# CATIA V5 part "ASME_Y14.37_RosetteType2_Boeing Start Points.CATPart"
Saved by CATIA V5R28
Part number: 333X3333-303
Revision: --
Nomenclature: ASME_Y14.37_RosetteType2
Bounding box of the stored display mesh (mm): x -188.298 to 149.059, y -714.612 to 664.697, z 0 to 91.639
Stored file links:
  C:\Users\jvl2147\Documents\AP242 testing\Composite Example Parts for PER\Start Points - CWB\ASME_Y14.37_RosetteType2_Boeing Start Points.CATPart
  \\NW\Data\MSE-Composites\ASME Y14.37\ASME Y-14.37_COMPOSITES.CATMaterial
  C:\Users\jvl2147\AppData\Local\DassaultSystemes\CATTemp\B28SP3PRALL\333X3333-303_Ply Group - 333X3333-303_StaggerOrigin.txt
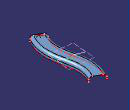
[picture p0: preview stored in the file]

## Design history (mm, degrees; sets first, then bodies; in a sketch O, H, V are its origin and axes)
AxisSystem1 "ROSETTE COORDINATE SYSTEM": origin (-72.9205, -637.9645, 93.98), X (0.5026, 0.8645, 0), Y (-0.8645, 0.5026, 0), Z (0, 0, 1)
CompParametersFeature1 "CATCoParametersFeatName": Value 0, Value 45, Value -45, Value 90
CompEOPGroupFeature1 "CATCoEOPGroupFeatName"
CompStacking1 "Stacking"
CompIsoThickAreasGroup1 "CATCoIsoThickAreasGroupFeatName": RefAddThickness 0
TTRSSet1
f4a2d38f3ddc11d3a929006094b99c4b_11 "CATTPSSet"
CompReviewTools1 "Review tools"
Set1 "CONSTRUCTION GEOMETRY"
  Set2 "CONSTRUCTION - LAMINATE REFERENCE SURFACE"
    Sketch1 on xy-plane, origin (0, 0, 0), H (1, 0, 0), V (0, 1, 0)
      spline S1 through (-79.505, -649.09) (21.2912, -260.3998) (-51.6257, 228.8061) (37.963, 602.845)
    Plane1: type Normal, Curve Sketch1, RefPoint vertex of Sketch1, Ratio 0
    Sketch2 on Plane1, origin (-464.3095, -417.3341, 0), H (-0.8566, 0.5159, 0), V (0, 0, 1)
      line L1 (-525.4052, 91.6386) -> (-373.0052, 91.6386)
      line L2 (-322.2052, 40.8386) -> (-322.2052, 0)
      line L3 (-576.2052, 0) -> (-576.2052, 40.8386)
      reference projected point E1 (-449.2052, 0) from vertex of Sketch1
      reference projected point E2 (-449.2052, 0) from vertex of Sketch1
      arc A1 centre (-373.0052, 40.8386) radius 50.8 from (-373.0052, 91.6386) to (-322.2052, 40.8386) cw
      arc A2 centre (-525.4052, 40.8386) radius 50.8 from (-576.2052, 40.8386) to (-525.4052, 91.6386) cw
      distance E1 L2 = 127
      distance E2 L3 = 127
      radius A1 = 50.8
      radius A2 = 50.8
      horizontal: L1 H
      vertical: L2 V, L3 V
      tangency: A1 L1, A1 L2, A2 L3, A2 L1
    Sweep1: type Unspec, Profile Sketch2, Guide Sketch1
  Set3 "CONSTRUCTION - PLIES EOPS"
    Plane2: type Normal, Curve Sketch1, RefPoint vertex of Sketch1, Ratio 0
    Plane3: type Normal, Curve Sketch1, RefPoint {point type OnCurve, Support Sketch1, Length 1118.262}, Ratio 0.99
    Plane4: type Normal, Curve Sketch1, Ratio 0.01
    Intersect1: ToIntersect1 Plane3, ToIntersect2 Sweep1
    Intersect2: ToIntersect1 Sweep1, ToIntersect2 Plane4
    Plane5: type Offset, RefPlane xy-plane, Offset 2.54
    Intersect3: ToIntersect1 Plane5, ToIntersect2 Join1
    Near1: MultiElement Intersect3, ReferenceElement edge of Sweep1
    Near2: MultiElement Intersect3, ReferenceElement edge of Sweep1
  Set4 "CONSTRUCTION - ROSETTE COORDINATE SYSTEM"
    Intersect4: ToIntersect1 Plane4, ToIntersect2 Project2
    Line1: type Tangency, RefPoint Intersect4, Curve Project2, Start 0, End 25.4
    Plane6: type Offset, RefPlane xy-plane, Offset 93.98
    Project1 "PROJECT": ToProject Sketch1, Support Join1, Direction xy-plane
  Set5 "CONSTRUCTION - ROSETTE TRANSFORMS"
    Line2 "Ply.1_Rosette_transfer_X": type Tangency, RefPoint {point type OnCurve, Support Project2, Length 288.56}, Curve Project2, Support Join1, Start 0, End 25.4
    Line3 "Ply.1_Rosette_transfer_X.Renamed": type Tangency, RefPoint {point type OnCurve, Support Project2, Length 536.186}, Curve Project2, Support Join1, Start 25.4, End 0
    Line4 "Ply.1_Rosette_transfer_X.Renamed": type Tangency, RefPoint {point type OnCurve, Support Project2, Length 783.62}, Curve Project2, Support Join1, Start 25.4, End 0
    Line5 "Ply.1_Rosette_transfer_X.Renamed": type Tangency, RefPoint {point type OnCurve, Support Project2, Length 1274.71}, Curve Project2, Support Join1, Start 25.4, End 0
    Line6 "Ply.1_Rosette_transfer_X.Renamed": type Tangency, RefPoint {point type OnCurve, Support Project2, Length 1017.245}, Curve Project2, Support Join1, Start 25.4, End 0
    AxisSystem2 "ROSETTE COORDINATE SYSTEM": origin (16.8931, -379.3831, 93.98), X (0.1242, 0.9923, 0), Y (-0.9923, 0.1242, 0), Z (0, 0, 1)
    AxisSystem3 "ROSETTE COORDINATE SYSTEM.Renamed": origin (7.1166, -132.8437, 93.98), X (-0.1632, 0.9866, 0), Y (-0.9866, -0.1632, 0), Z (0, 0, 1)
    AxisSystem4 "ROSETTE COORDINATE SYSTEM.Renamed1": origin (-38.9217, 110.2518, 93.98), X (-0.1571, 0.9876, 0), Y (-0.9876, -0.1571, 0), Z (0, 0, 1)
    AxisSystem5 "ROSETTE COORDINATE SYSTEM.Renamed2": origin (29.3229, 586.9432, 93.98), X (0.4677, 0.8839, 0), Y (-0.8839, 0.4677, 0), Z (0, 0, 1)
    AxisSystem6 "ROSETTE COORDINATE SYSTEM.Renamed3": origin (-47.995, 342.9553, 93.98), X (0.1137, 0.9935, 0), Y (-0.9935, 0.1137, 0), Z (0, 0, 1)
    Point1: type OnSurface, Support Join1, Length 362.156, Direction (-0.4364, -0.3881, 0.8118)
    Line7: type Normal, RefPoint Point1, RefSkin Join1, Start 254, End 0
  Plane7: type Offset, RefPlane YZ plane of AxisSystem2, Offset 0
  Circle1: type CtrRad, Start 0, End 180, Center {point type OnSurface, Support Join1, Length 336.531, Direction (0.5738, 0.5102, 0.6407)}, Support Join1, Radius 50.8, FirstDirection (1, 0, 0)
  CurvePar1: Offset Near1, Support Join1, Offset2 0, Offset1 50.8
Set6 "ENGINEERING GEOMETRY"
  Set7 "LAMINATE REFERENCE SURFACE"
    Join1 "LAMINATE REFERENCE SURFACE": Elements Sweep1
  Set8 "GUIDE CURVE - ZERO DEGREE ORIENTATION"
    Project2 "GUIDE CURVE - 0°": ToProject Sketch1, Support Plane6
Body1 (main body)
Body2 "-303"
  CompIsoThickAreasSolid1 "Area Solid.1": IsoAreasGroup CompIsoThickAreasGroup1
